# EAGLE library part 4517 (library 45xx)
Dual 64-bit static REGISTER
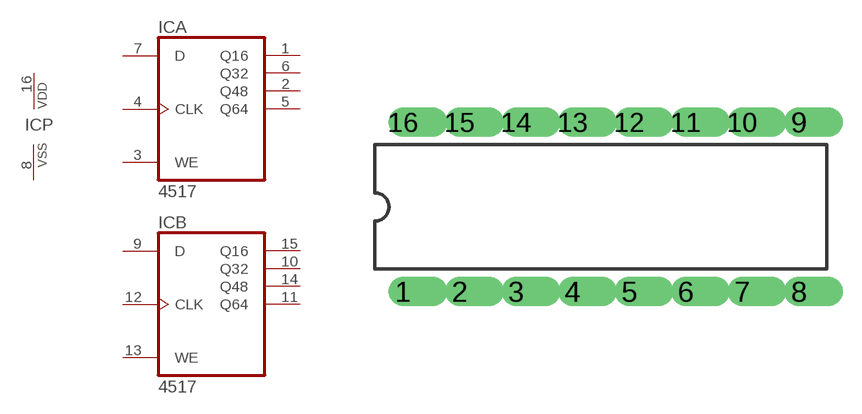
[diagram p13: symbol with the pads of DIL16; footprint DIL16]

Designator prefix IC; gates A=4517 B=4517 P=PWRN

## 4517N  [DIL16]
1  A:Q16  out
2  A:Q48  out
3  A:WE  in
4  A:CLK  in
5  A:Q64  out
6  A:Q32  out
7  A:D  in
8  P:VSS  pwr
9  B:D  in
10  B:Q32  out
11  B:Q64  out
12  B:CLK  in
13  B:WE  in
14  B:Q48  out
15  B:Q16  out
16  P:VDD  pwr

## Footprint DIL16 (pad centres in mm)
Dual In Line
drill 0.813 offset: 1 -8.89,-3.81; 2 -6.35,-3.81; 3 -3.81,-3.81; 4 -1.27,-3.81; 5 1.27,-3.81; 6 3.81,-3.81; 7 6.35,-3.81; 8 8.89,-3.81; 9 8.89,3.81; 10 6.35,3.81; 11 3.81,3.81; 12 1.27,3.81; 13 -1.27,3.81; 14 -3.81,3.81; 15 -6.35,3.81; 16 -8.89,3.81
